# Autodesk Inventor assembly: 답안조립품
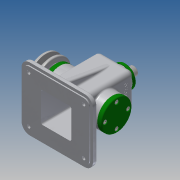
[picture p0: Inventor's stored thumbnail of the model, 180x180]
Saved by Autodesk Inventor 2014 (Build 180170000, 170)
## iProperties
Created: 2015-12
Part Number: 답안조립품
Document SubType Name: Assembly
Designer: Administrator
Author: Administrator
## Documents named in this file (19)
- D:\이도연\451225V1011\답안조립품.iam
- D:\이도연\451225V1011\1-본체.ipt
- D:\이도연\451225V1011\편심축.ipt
- D:\이도연\451225V1011\키 5 x 5 x 14.ipt
- D:\이도연\451225V1011\링크.ipt
- D:\이도연\451225V1011\슬라이드바.ipt
- D:\이도연\451225V1011\고정핀.ipt
- D:\이도연\451225V1011\멈춤링 6 x 5.ipt
- D:\이도연\451225V1011\뒤커버.ipt
- D:\이도연\451225V1011\볼트 M4 x 10.ipt
- D:\이도연\451225V1011\베어링 15 x 35 x 11.ipt
- D:\이도연\451225V1011\앞커버.ipt
- D:\이도연\451225V1011\상부부시.ipt
- D:\이도연\451225V1011\볼트 M3 x 8.ipt
- D:\이도연\451225V1011\멈춤링 15 x 1.ipt
- D:\이도연\451225V1011\V-벨트풀리.ipt
- D:\이도연\451225V1011\오일실 15 25 7.ipt
- D:\이도연\451225V1011\와셔.ipt
- D:\이도연\451225V1011\볼트 M6 x 12.ipt
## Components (16 placed, 6 different names)
1. 1-본체:1
2. 고정핀:1 — 플러쉬:2
3. V-벨트풀리:1 — 플러쉬:3
4. ISO 4018 M6 x 12:1
5. ISO 4762 M4 x 10:1
6. ISO 4762 M4 x 10:2
7. ISO 4762 M4 x 10:3
8. ISO 4762 M4 x 10:4
9. ISO 4762 M4 x 10:5
10. ISO 4762 M4 x 10:6
11. ISO 4762 M4 x 10:7
12. ISO 4762 M4 x 10:8
13. ISO 4762 M3 x 8:1
14. ISO 4762 M3 x 8:2
15. ISO 4762 M3 x 8:3
16. ISO 4762 M3 x 8:4
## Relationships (2: Flush 2)
- 플러쉬:2 [Flush]: 고정핀:1
- 플러쉬:3 [Flush]: V-벨트풀리:1
